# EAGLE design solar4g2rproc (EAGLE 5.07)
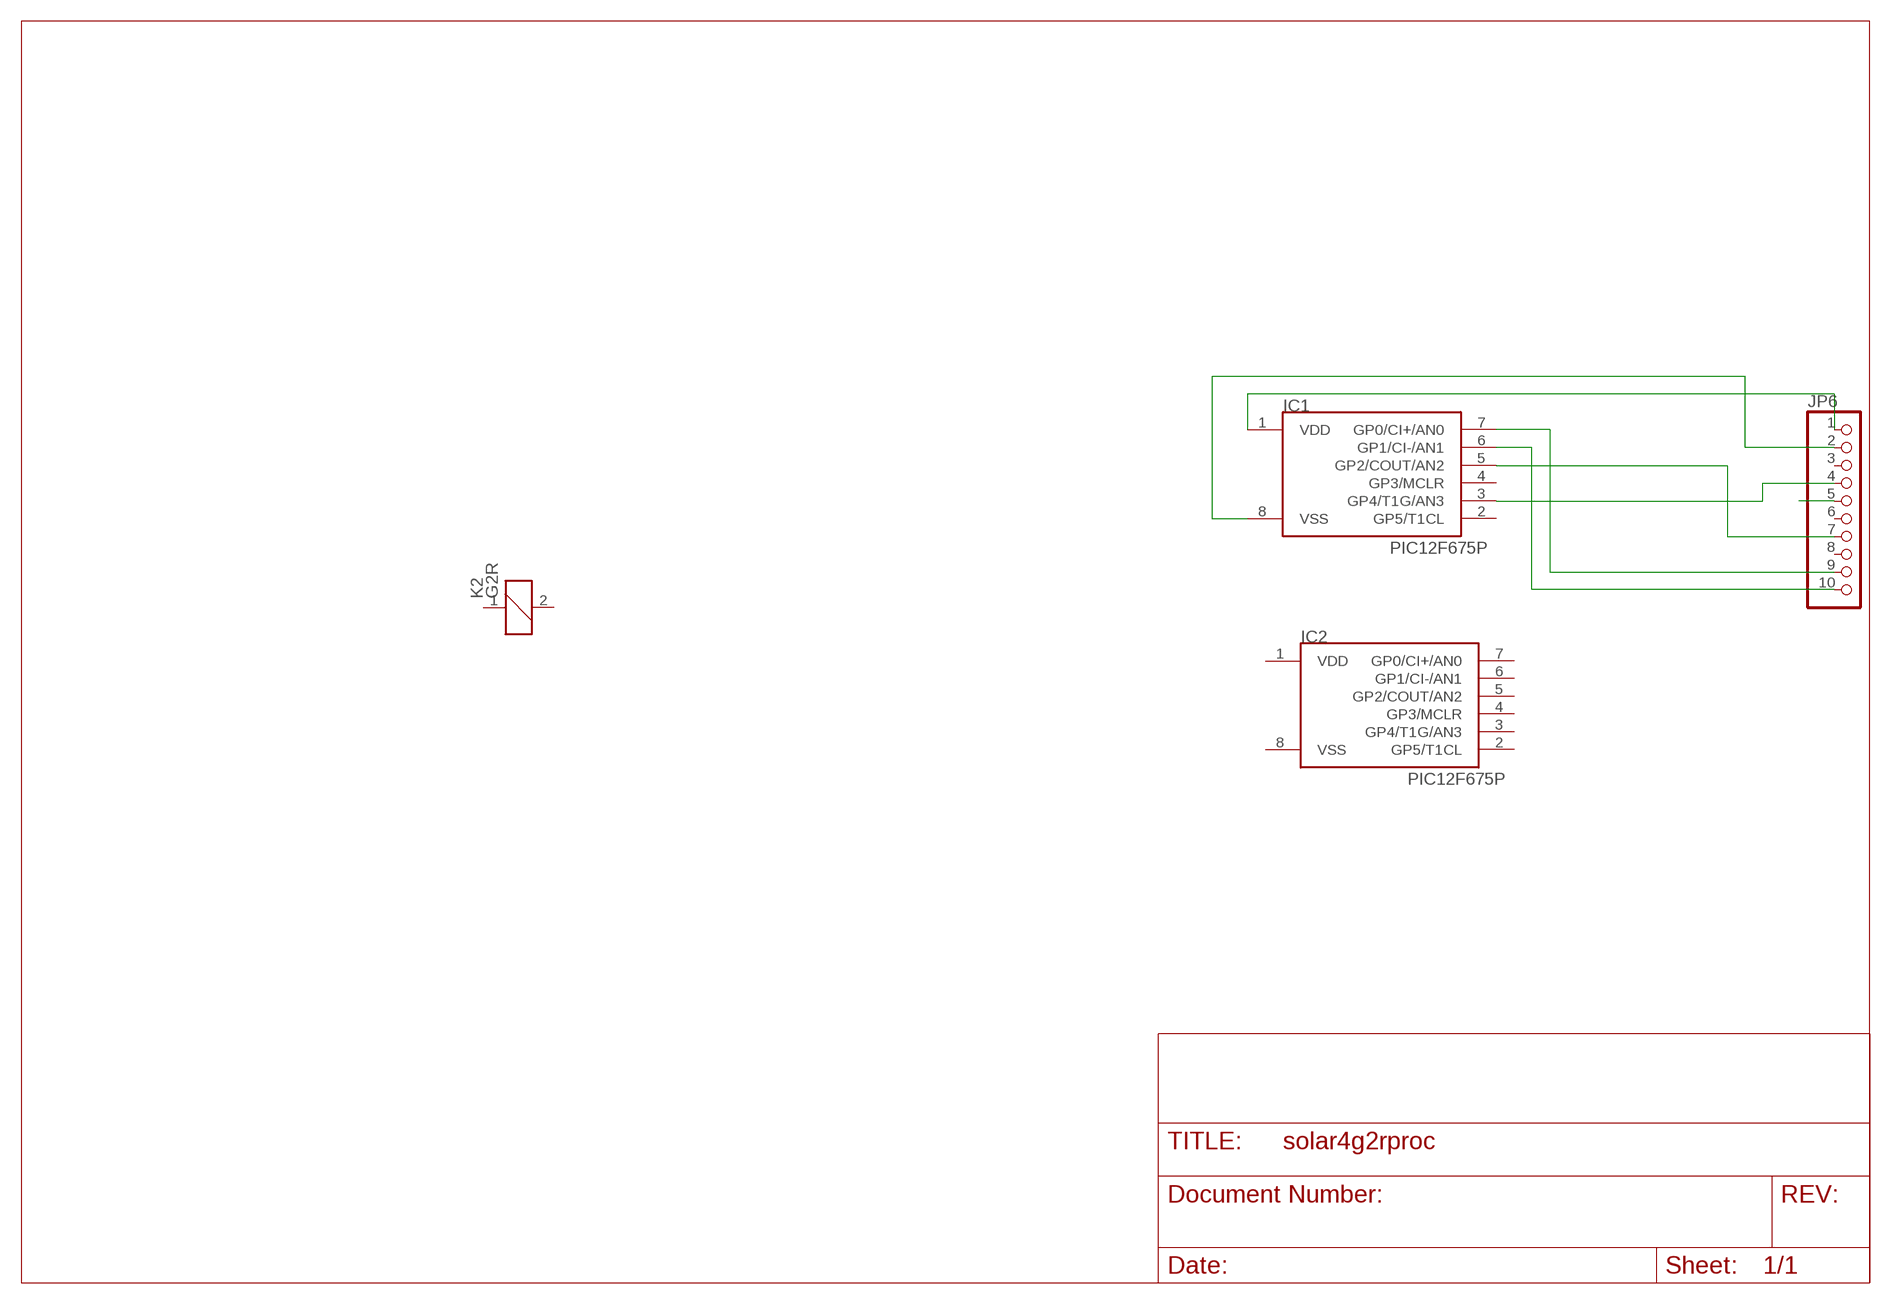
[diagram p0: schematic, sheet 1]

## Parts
IC1  PIC12F675P  [DIL8]
IC2  PIC12F675P  [DIL8]
JP6  PINHD-1X10  [1X10]
K2  G2R  [G2R]

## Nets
N$1: IC1.8(VSS) JP6.2
N$2: IC1.5(GP2/COUT/AN2) JP6.7
N$3: IC1.7(GP0/CI+/AN0) JP6.9
N$4: IC1.6(GP1/CI-/AN1) JP6.10
N$6: IC1.3(GP4/T1G/AN3) JP6.4
N$48: JP6.5
N$51: IC1.1(VDD) JP6.1
Unconnected: IC1.2(GP5/T1CL) IC1.4(GP3/MCLR) IC2.2(GP5/T1CL) IC2.3(GP4/T1G/AN3) IC2.4(GP3/MCLR) IC2.5(GP2/COUT/AN2) IC2.6(GP1/CI-/AN1) IC2.7(GP0/CI+/AN0) JP6.3 JP6.6 JP6.8 K2.1 K2.2 K2.O(2:O) K2.P(2:P) K2.S(2:S)

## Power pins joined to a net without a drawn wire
VDD: IC2.1(VDD)
VSS: IC2.8(VSS)

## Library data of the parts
IC1 IC2 = microchip-5:PIC12F6*: uPC nW 1k Program Flash memory 2x Timer Comparator 10b A/D converter/ 4xIN
JP6 = pinhead:PINHD-1X10: PIN HEADER
K2 = relay:G2R: RELAY 1 x switch, Omron

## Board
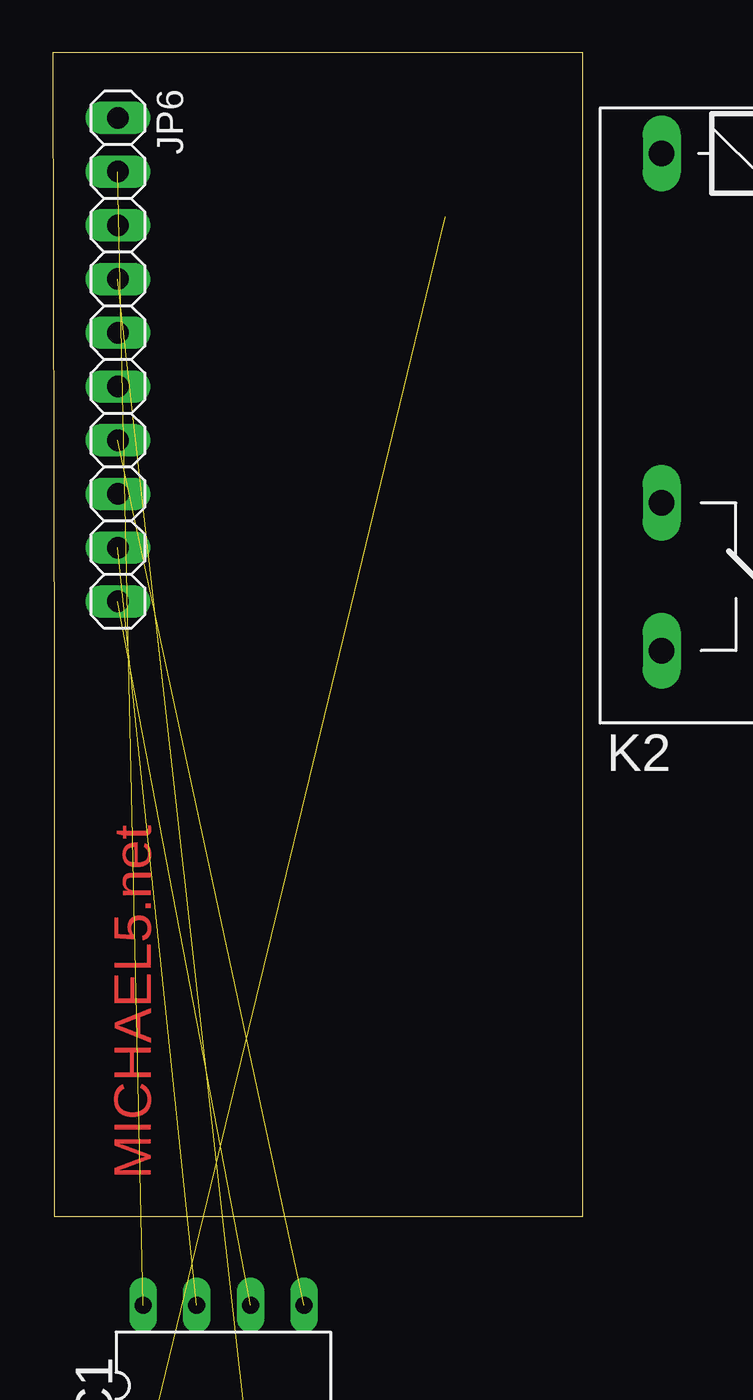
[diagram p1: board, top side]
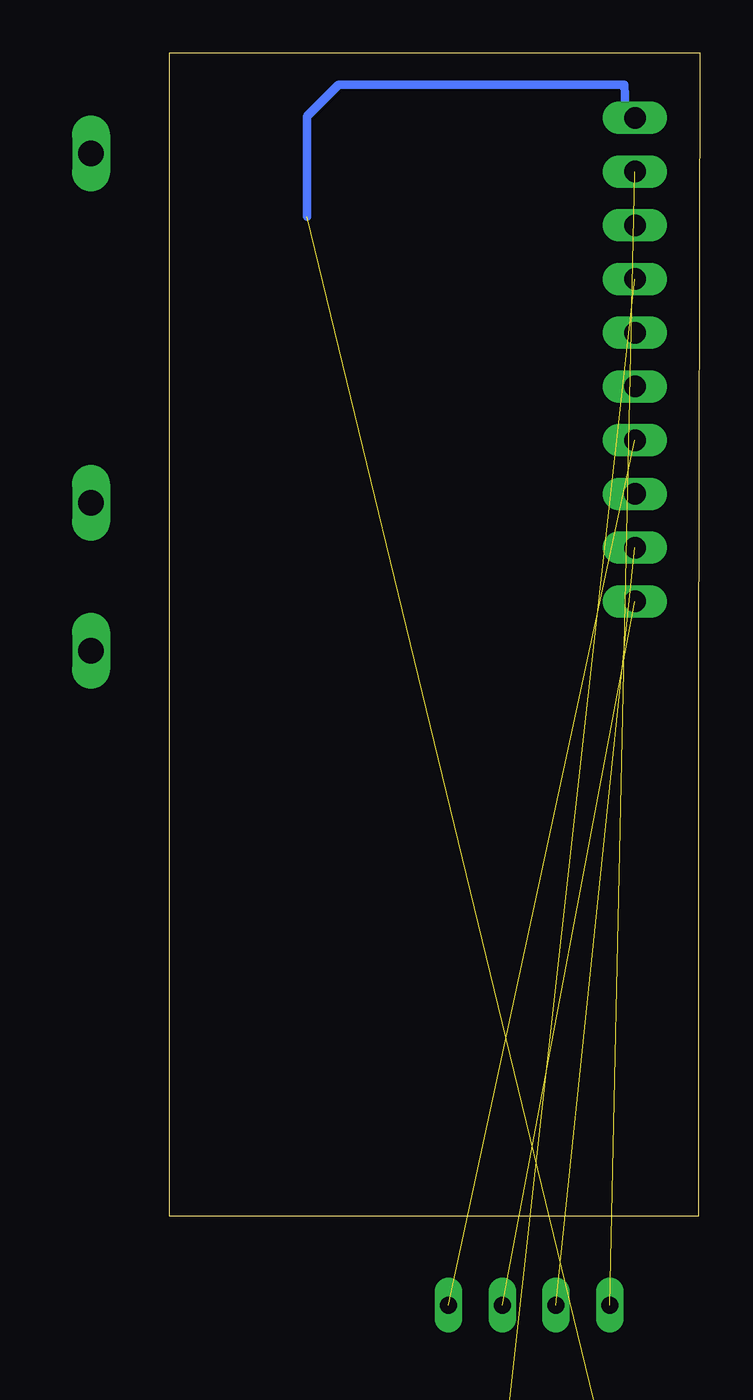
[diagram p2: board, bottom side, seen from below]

Size 25.07 x 55 mm. Coordinates in mm from the lower left corner, seen from the top.
Outline: 0.07,0 25.07,0 25.07,55 0,55 0.07,25 0.07,0
Copper layers (1*16): Top 0.035mm / dielectric 1.5mm / Bottom 0.035mm
Design rules "default *": minimum track width 40mil, minimum drill 30mil, track to track 8mil, track to pad 8mil, pad to pad 8mil, via to via 8mil, smd to smd 8mil, copper to edge 40mil, drill to drill 8mil, minimum pad ring 10mil, minimum via ring 8mil, stop-mask expansion 4mil, vias tented up to drill 0mil, thermal gap 10mil

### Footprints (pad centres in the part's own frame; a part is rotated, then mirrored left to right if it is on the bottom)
DIL8 = drill 0.8 long: 1 -3.81,-3.81; 2 -1.27,-3.81; 3 1.27,-3.81; 4 3.81,-3.81; 5 3.81,3.81; 6 1.27,3.81; 7 -1.27,3.81; 8 -3.81,3.81
1X10 = drill 1.016 long: 1 -11.43,0; 2 -8.89,0; 3 -6.35,0; 4 -3.81,0; 5 -1.27,0; 6 1.27,0; 7 3.81,0; 8 6.35,0; 9 8.89,0; 10 11.43,0
G2R = drill 1.2 pad 1.778 long: 1 -2.54,-3.683; 2 -2.54,3.81; O 13.97,-3.683; P 17.45,3.81; S 20.955,-3.683

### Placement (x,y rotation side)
IC1  not placed on the board
IC2  not placed on the board
JP6  3.07,40.5 270 top
K2  not placed on the board

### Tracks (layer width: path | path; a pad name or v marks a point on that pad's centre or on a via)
N$1  (1 unrouted)
N$2  (1 unrouted)
  Bottom 0.813: JP6.7 3.38,37
N$3  (1 unrouted)
N$4  (1 unrouted)
N$6  (1 unrouted)
N$48
  Bottom 0.813: JP6.5 3.3,42
N$51  (1 unrouted)
  Bottom 0.406: 3.5,51.93 3.57,53.5 17.07,53.5 18.57,52 18.57,47.27
  Bottom 0.813: JP6.1 3.5,51.93

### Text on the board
Top: MICHAEL5.net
